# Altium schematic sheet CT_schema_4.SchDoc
size 218 x 258 mm
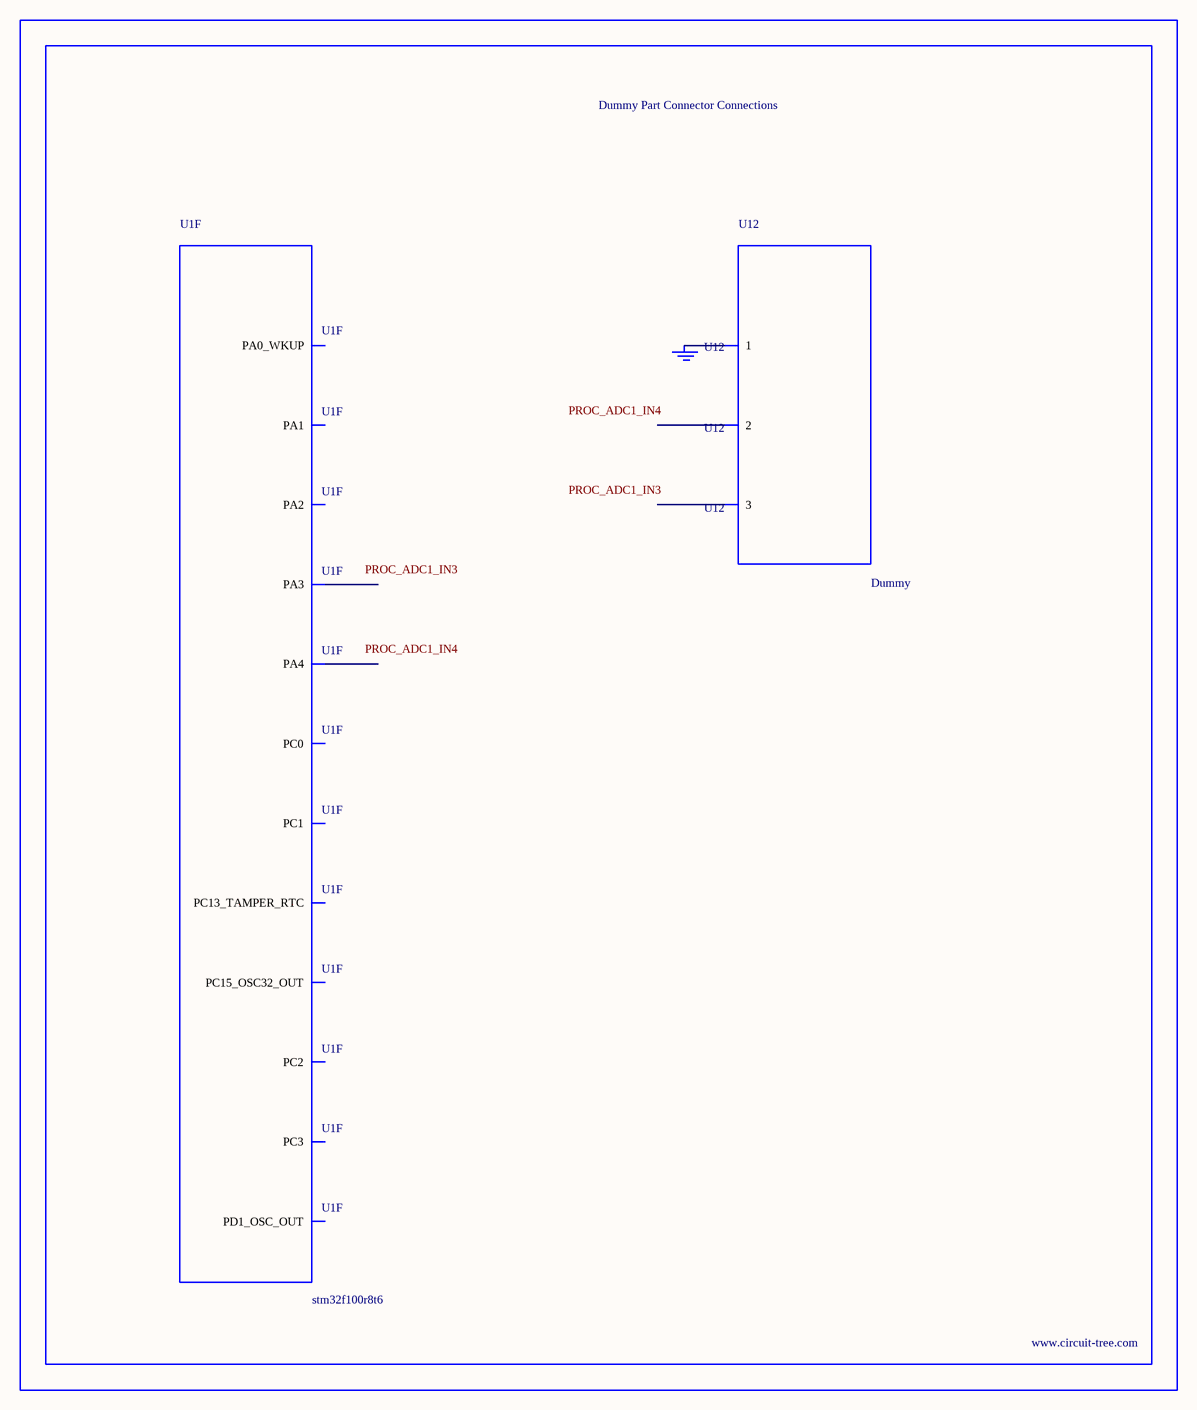
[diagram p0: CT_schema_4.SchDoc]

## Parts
BORDER3  (no value)
GND_INSTANCE_3_0  (no value)
U1  stm32f100r8t6  [LQFP64]  (part F of 6)
U12  Dummy  [DUMMY_PACKAGE_124]

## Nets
NetGND_INSTANCE_3_0_0: GND_INSTANCE_3_0.0(GND) U12.1

Not connected (* = marked no-connect by the designer): U1 2(PC13_TAMPER_RTC) 4(PC15_OSC32_OUT) 6(PD1_OSC_OUT) 8(PC0) 9(PC1) 10(PC2) 11(PC3) 14(PA0_WKUP) 15(PA1) 16(PA2) 17(PA3) 20(PA4); U12 2 3

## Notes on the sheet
- Labels drawn without touching a wire or pin: PROC_ADC1_IN3, PROC_ADC1_IN4

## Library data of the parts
BORDER3 = BORDER_PAGE3
GND_INSTANCE_3_0 = GND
